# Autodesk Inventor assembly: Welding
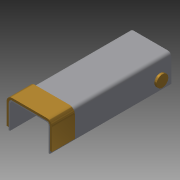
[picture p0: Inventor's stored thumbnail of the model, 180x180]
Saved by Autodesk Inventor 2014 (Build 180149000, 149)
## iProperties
Shininess: 64.0
Length Units: 11269
Angle Units: 11279
Time Units: 11290
Mass Units: 11283
Length Display Precision: 3
Angle Display Precision: 2
Created: 2002-08
Part Number: Welding
Document SubType Name: Assembly
Designer: t_munrn
Mass: 2822.73 g
Surface Area: 8368.81 cm^2
Volume: 2822.73 cm^3
Density: 1 g/cm^3
Density: 0.0
Volumn: 0.0
Area: 0.0
PropertySet Name: Model Information
Control State: 0
Master: False
Checked Out: False
Author: t_munrn
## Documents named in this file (4)
- C:\Users\iTools\Desktop\tutorial files\Weldments\Welding.iam
- C:\Users\iTools\Desktop\tutorial files\Weldments\Channel.ipt
- C:\Users\iTools\Desktop\tutorial files\Weldments\Brace.ipt
- C:\Users\iTools\Desktop\tutorial files\Weldments\Hole_Plate.ipt
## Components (4 placed, 3 different names)
1. Channel:1 — Flush:1, Mate:1, Flush:2, Flush:3, Flush:4, Mate:2, Mate:3
2. Brace:1 — Flush:1, Mate:1, Flush:2
3. Hole_Plate:1 — Flush:3, Flush:4, Mate:2, Mate:4
4. Hole_Plate:2 — Mate:3, Mate:4
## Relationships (8: Flush 4, Mate 4)
- Flush:1: Channel:1 ↔ Brace:1
- Mate:1: Channel:1 ↔ Brace:1
- Flush:2: Channel:1 ↔ Brace:1
- Flush:3: Channel:1 ↔ Hole_Plate:1
- Flush:4: Channel:1 ↔ Hole_Plate:1
- Mate:2: Channel:1 ↔ Hole_Plate:1
- Mate:3: Channel:1 ↔ Hole_Plate:2
- Mate:4: Hole_Plate:1 ↔ Hole_Plate:2
